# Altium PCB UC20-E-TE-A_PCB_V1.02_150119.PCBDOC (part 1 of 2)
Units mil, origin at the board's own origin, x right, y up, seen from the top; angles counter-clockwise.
Board outline 1460.63 x 2271.65 mil, 4 copper layers (Top, Inner Layer 2, Inner Layer 3, Bottom), stack 35.4 mil thick; 44 components, 79 nets, 323 pads, 599 vias.
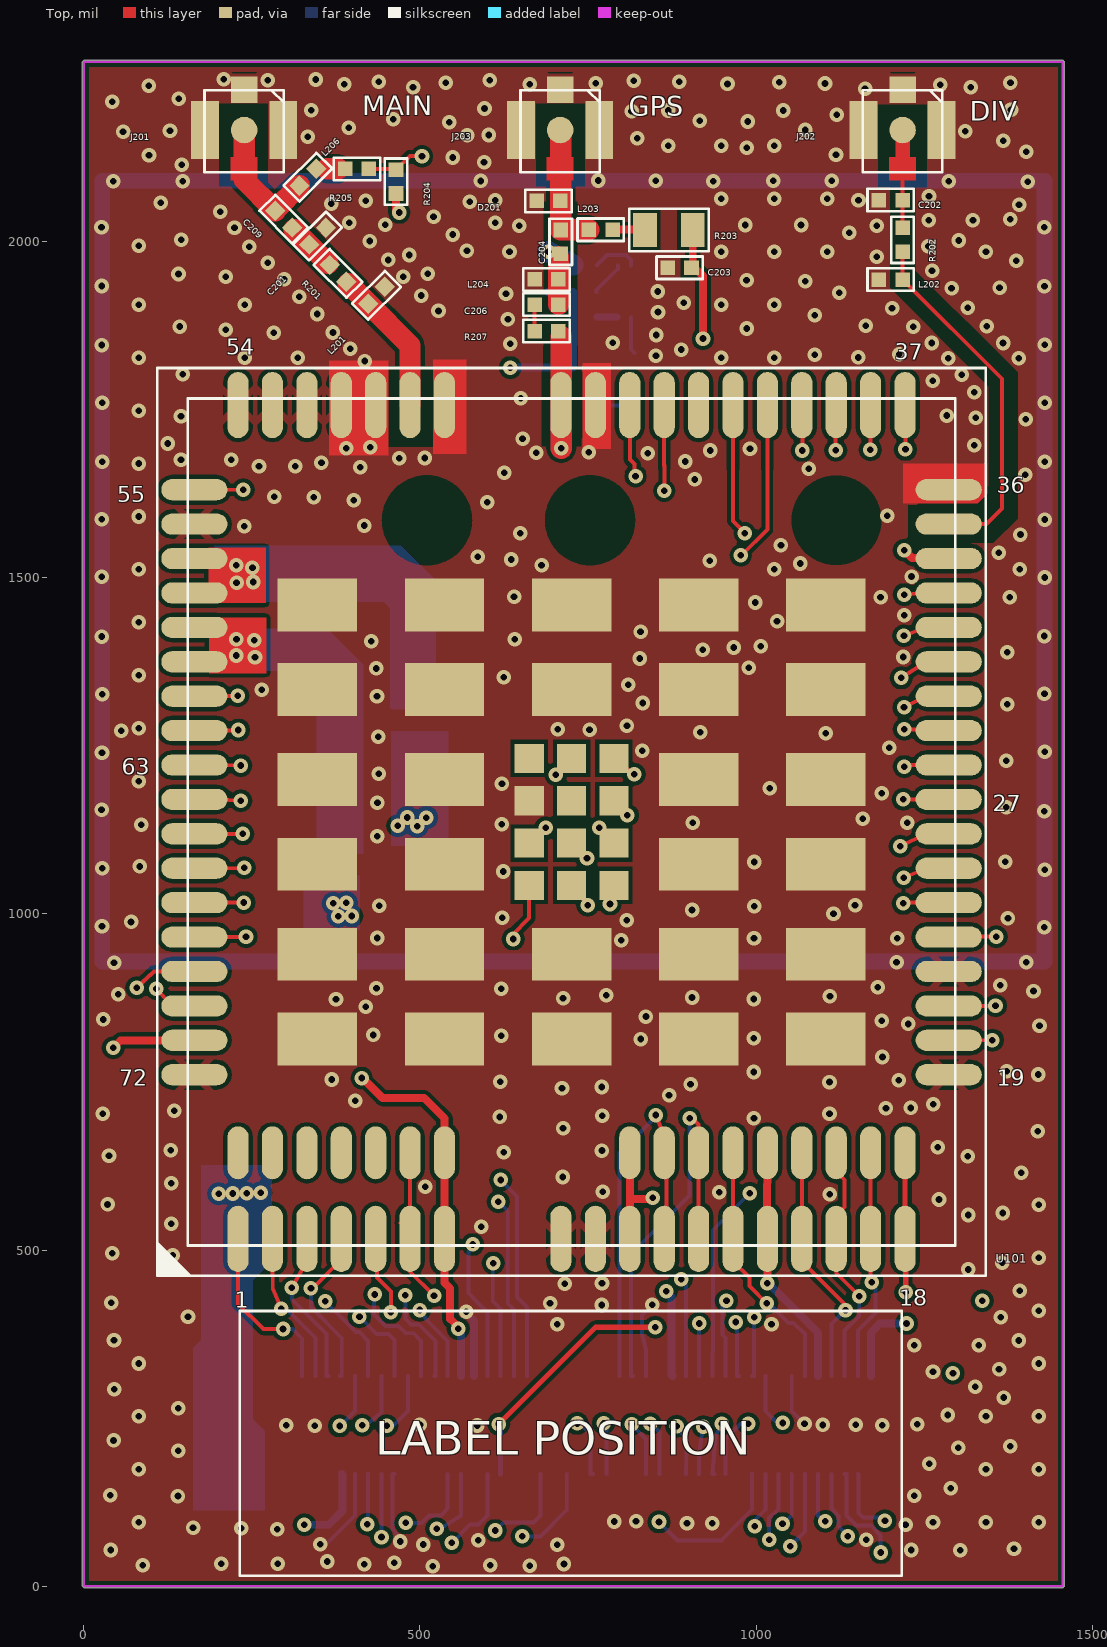
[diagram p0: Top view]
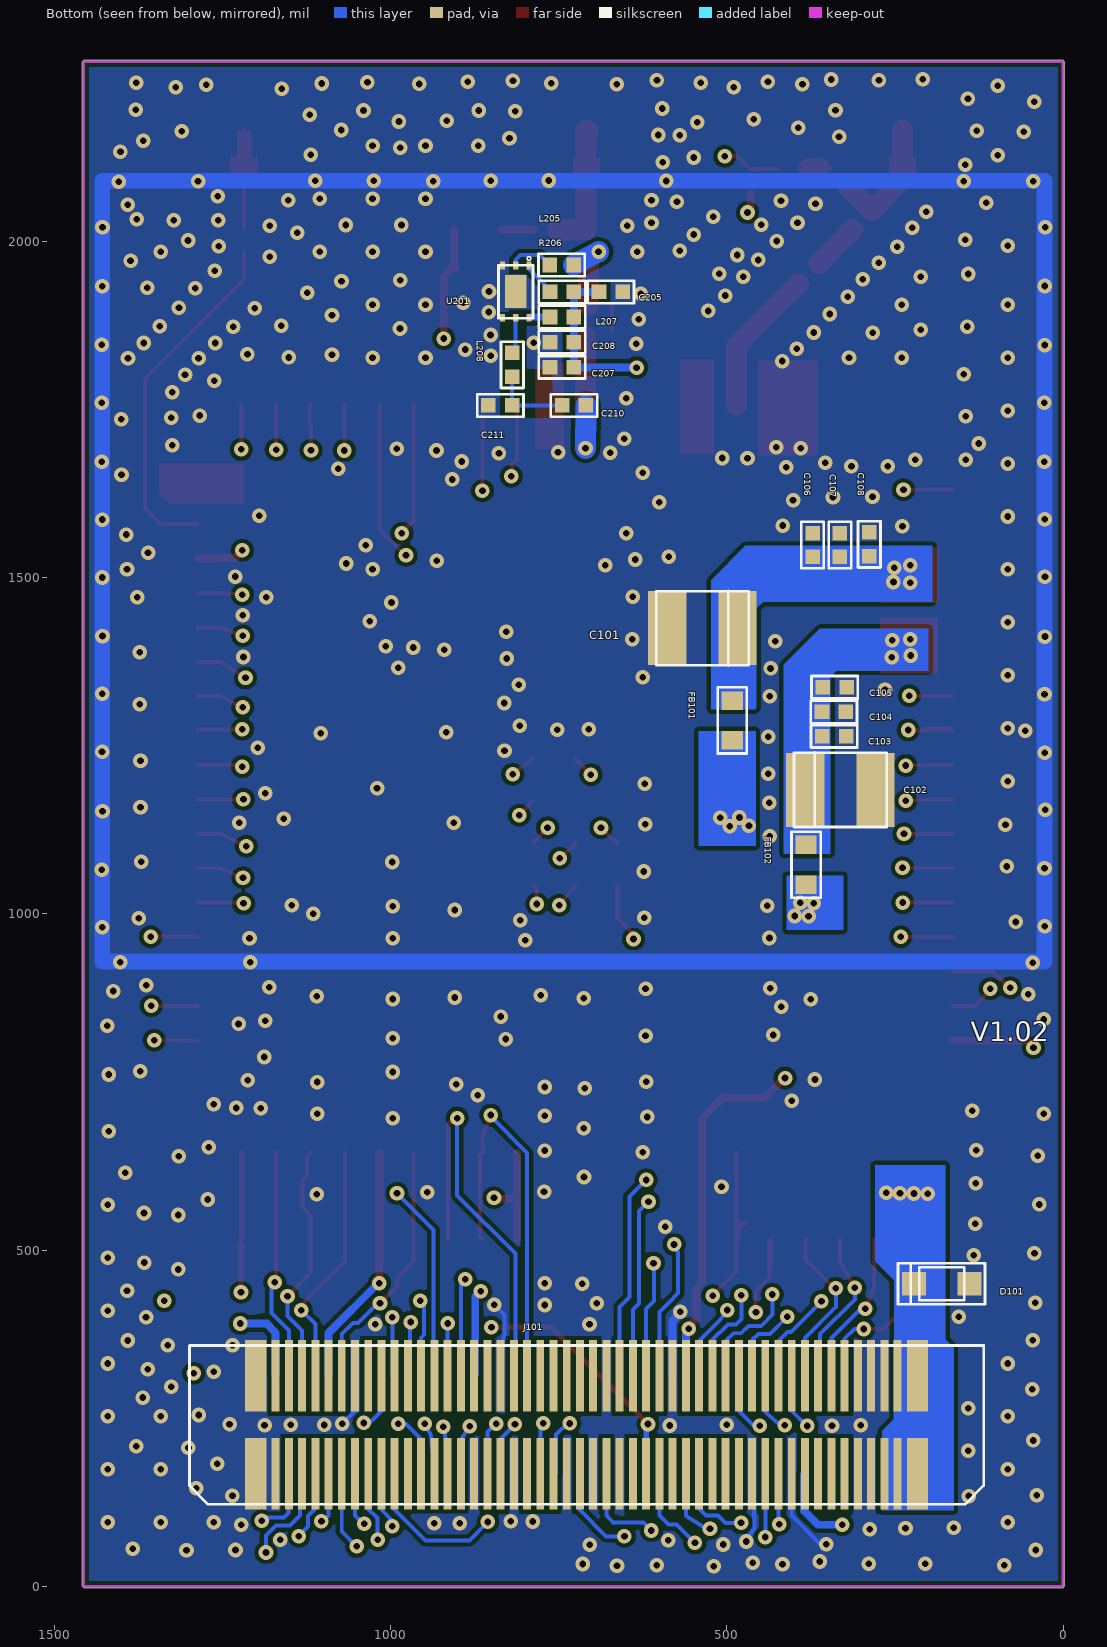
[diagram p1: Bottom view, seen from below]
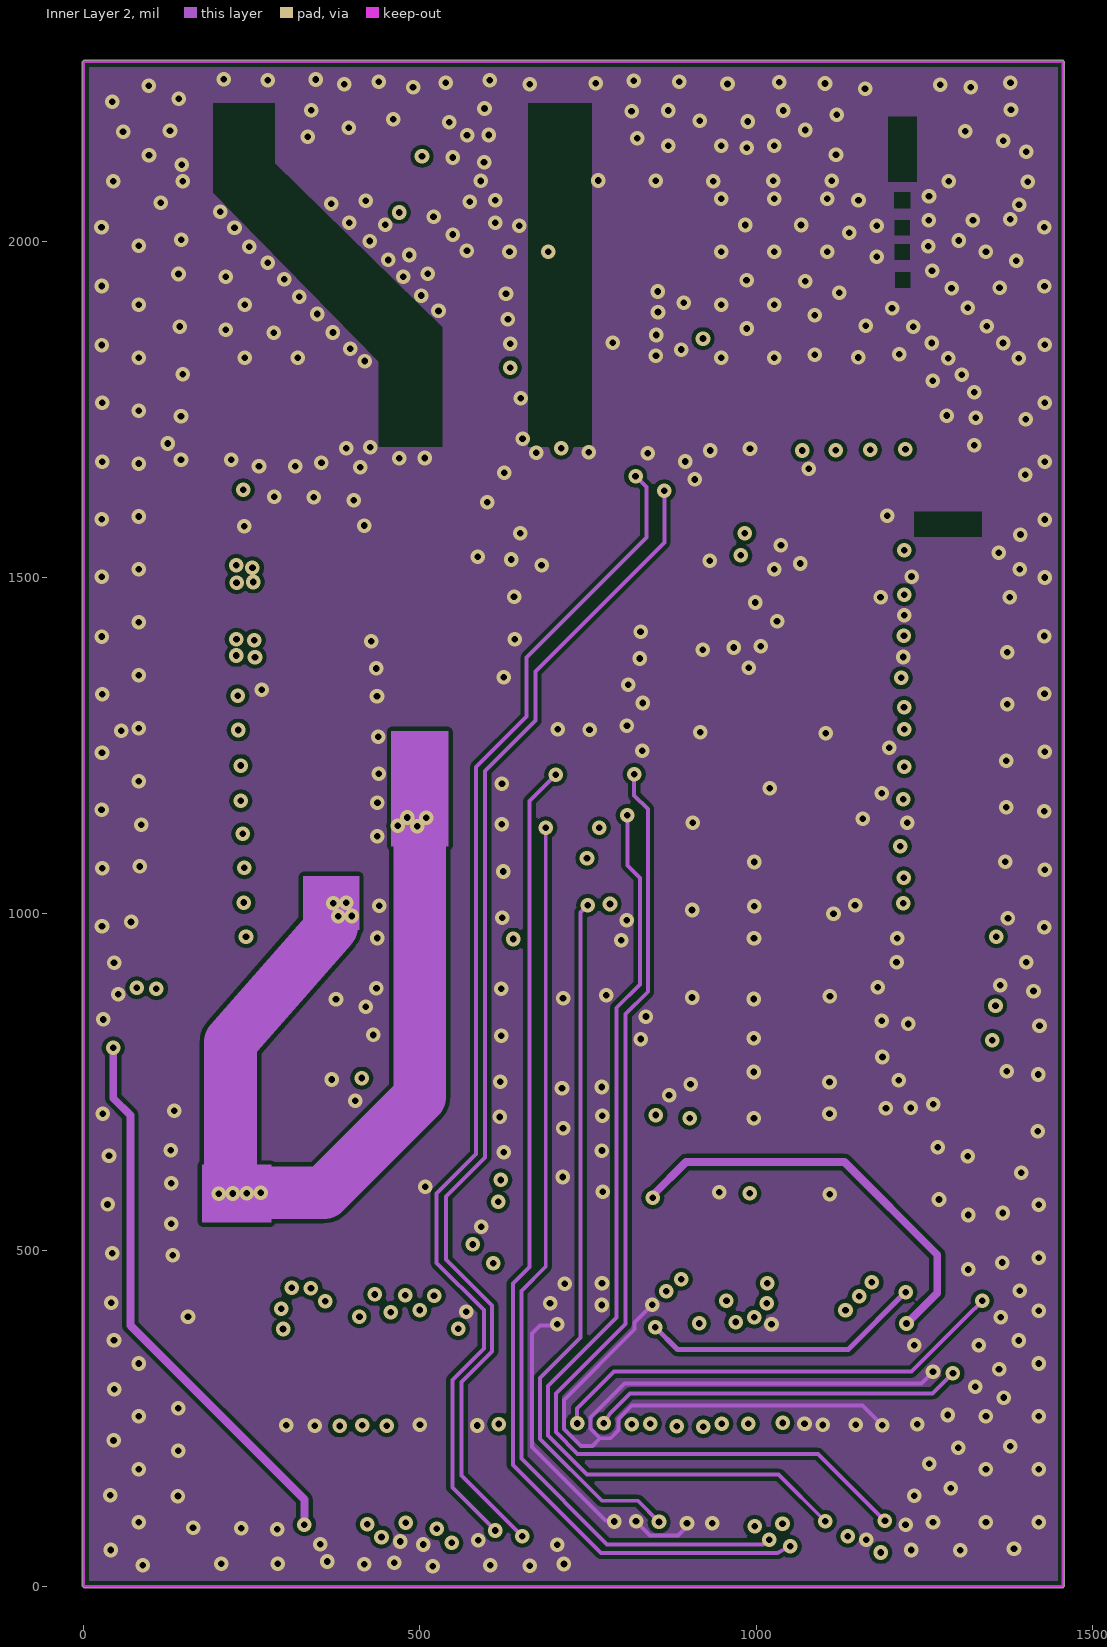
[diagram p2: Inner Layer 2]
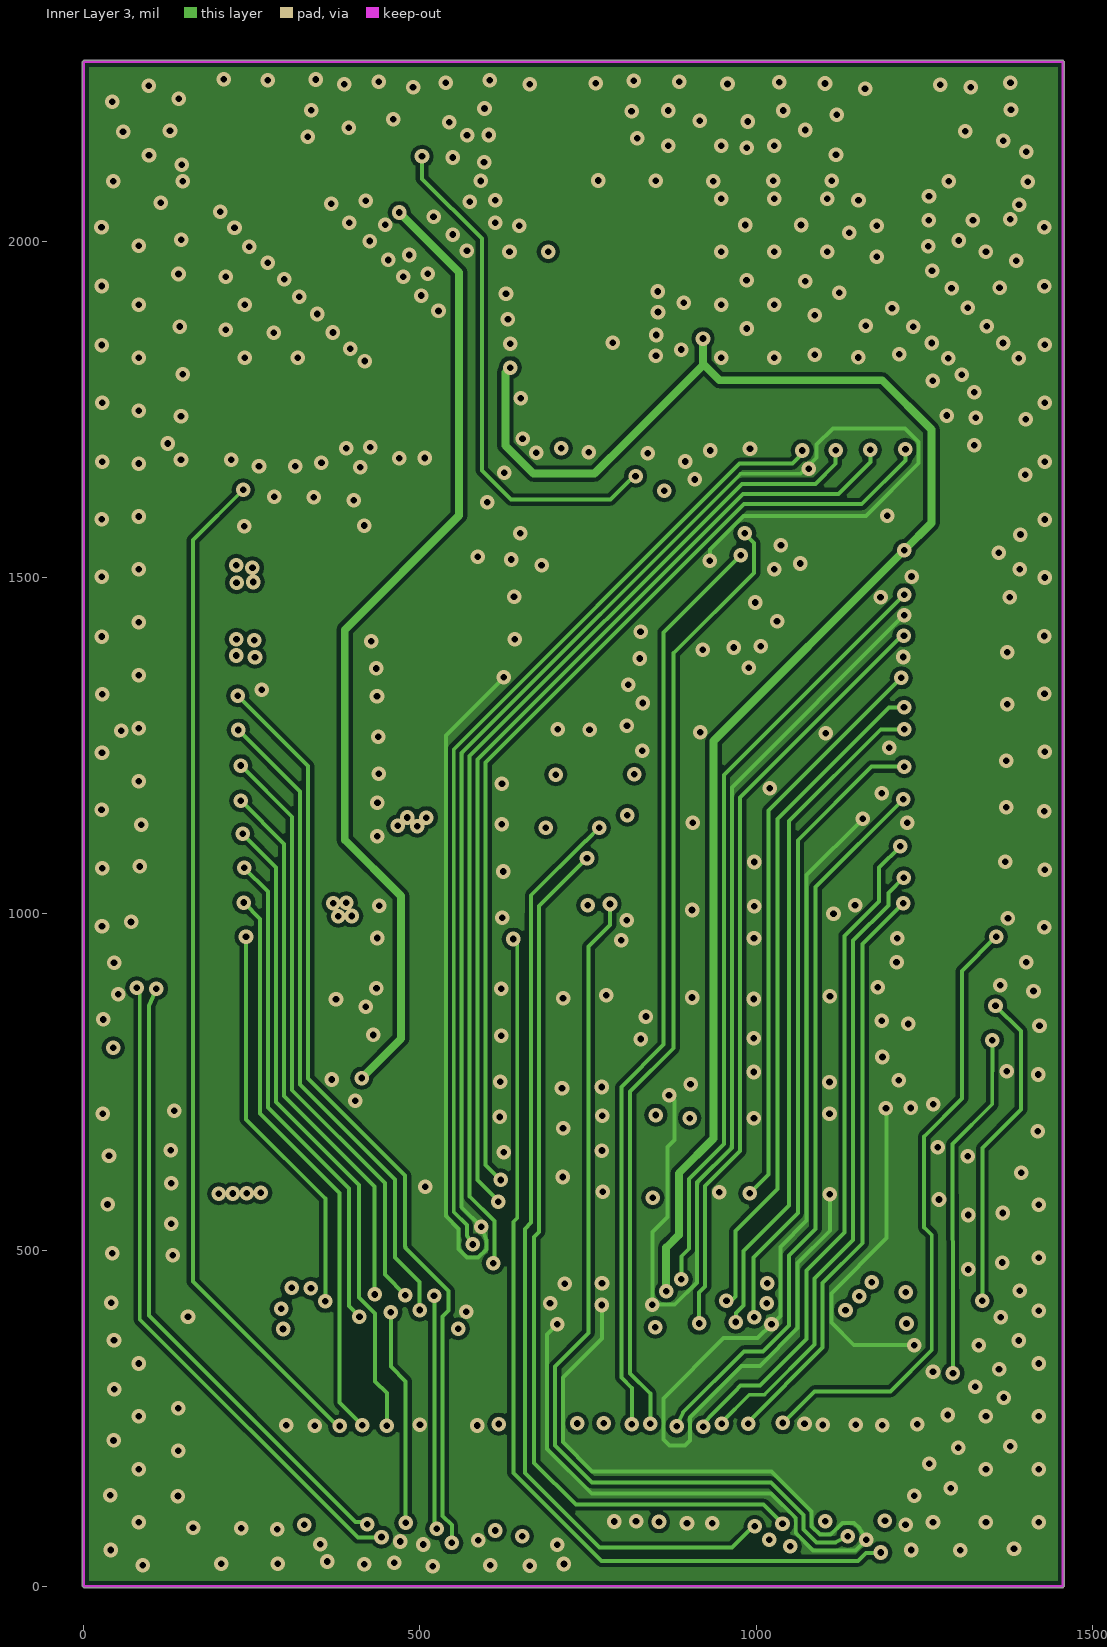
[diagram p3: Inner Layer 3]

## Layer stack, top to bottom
Top: signal copper 1.35
Dielectric: dielectric 10, FR-4, Dk 4.3
Inner Layer 2: signal copper 1.35
Dielectric: dielectric 10, FR-4, Dk 4.3
Inner Layer 3: signal copper 1.35
Dielectric: dielectric 10, FR-4, Dk 4.3
Bottom: signal copper 1.35

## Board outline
-1.97,0 0,-1.97 1456.69,-1.97 1458.66,0 1458.66,2267.72 1456.69,2269.68 0,2269.68 -1.97,2267.72

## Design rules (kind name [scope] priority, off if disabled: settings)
Clearance "'Default' PADS rule_18" [All] p1: gap=5.91
Clearance "'Default' PADS rule_15" [IsVia vs OnLayer(all)] p2: gap=0
ComponentClearance "'Default' PADS rule_12" [All] p1: gap=6 collisioncheckmode=3 verticalgap=10
FlightTimeFalling "'Default' PADS rule_6" [All] p1: maximum=10.00
FlightTimeRising "'Default' PADS rule_5" [All] p1: maximum=10.00
Length "'Default' PADS rule" [All] p1: maxlimit=50000 minlimit=0
MatchedLengths "'Default' PADS rule_7" [InNetClass('All Nets')] p1: tolerance=200 checknetsindiffpair=TRUE checkdiffpairvsdiffpair=TRUE checkothers=TRUE
MaxMinImpedance "'Default' PADS rule_4" [All] p1: minimum=50.00 maximum=150.0
ParallelSegment "'Default' PADS rule_3" [All] p1: limit=1000 gap=200
ParallelSegment "'Default' PADS rule_2" [All] p2: limit=1000 gap=200
PlaneClearance "'Net' PADS rule_34" [InNet('USB_DM')] p1: clearance=5.91
PlaneClearance "'Net' PADS rule_31" [InNet('$$$5208')] p2: clearance=5.91
PlaneClearance "'Net' PADS rule_27" [InNet('USB_DP')] p3: clearance=5.91
PlaneClearance "'Net' PADS rule_25" [InNet('ANT_MAIN')] p4: clearance=5.91
PlaneClearance "'Net' PADS rule_23" [InNet('GPS_IN')] p5: clearance=5.91
PlaneClearance "'Net' PADS rule_21" [InNet('$$$5265')] p6: clearance=5.91
PlaneClearance "'Net' PADS rule_19" [InNet('ANT_GPS')] p7: clearance=5.91
PlaneClearance "'Default' PADS rule_14" [All] p8: clearance=7.87
PlaneConnect "Power Plane Connect Style - from global settings" [All] p1: planeconnectstyle=Relief reliefexpansion=20 reliefentries=2 reliefconductorwidth=15 reliefairgap=10
PolygonConnect LCC [IsPad vs OnLayer('L1')] p1: connectstyle=Relief reliefconductorwidth=10 reliefentries=4 polygonreliefangle="45 Angle"
PolygonConnect PolygonConnect_1 [All] p2: connectstyle=Direct reliefconductorwidth=10 reliefentries=4 polygonreliefangle="90 Angle"
PolygonConnect LGA [IsPad] p3: connectstyle=Relief reliefconductorwidth=10 reliefentries=4 polygonreliefangle="45 Angle"
PolygonConnect GND-Via [IsVIA] p4: connectstyle=Direct reliefconductorwidth=10 reliefentries=4 polygonreliefangle="90 Angle"
PolygonConnect [All] p5: connectstyle=Direct reliefconductorwidth=10 reliefentries=4 polygonreliefangle="90 Angle"
RoutingLayers "'Default' PADS rule_10" [All] p1: top layer_v5=TRUE mid layer 1_v5=TRUE mid layer 2_v5=TRUE bottom layer_v5=TRUE
RoutingPriority "'Default' PADS rule_9" [All] p1: routingpriority=3
RoutingTopology "'Default' PADS rule_8" [All] p1: topology=Shortest
RoutingVias "'Default' PADS rule_11" [All] p1: holewidth=9.84 width=21.65 viastyle="Through Hole" minholewidth=9.84 minwidth=21.65 maxholewidth=9.84 maxwidth=21.65
SMDToCorner "'Default' PADS rule_16" [All] p1: distance=60000
SMDToPlane "'Default' PADS rule_17" [All] p1: distance=60000
SolderMaskExpansion [All] p1: expansion=4
TestPointUsage [All] p1: valid=0 allowmultiple=FALSE
Testpoint [All] p1: side=15 testpointundercomponent=TRUE minsize=40 maxsize=100 preferedsize=60 minholesize=0 maxholesize=40 preferedholesize=32 testpointgrid=1 style=1023 order=0-112345678
Width "'Net' PADS rule_33" [InNet('USB_DM')] p1: maxlimit=12 minlimit=3.94 preferedwidth=5.91
Width "'Net' PADS rule_32" [InNet('VDD_EXT')] p2: maxlimit=12 minlimit=3.94 preferedwidth=11.81
Width "'Net' PADS rule_30" [InNet('$$$5208')] p3: maxlimit=39.37 minlimit=3.94 preferedwidth=31.5
Width "'Net' PADS rule_29" [InNet('GND')] p4: maxlimit=12 minlimit=3.94 preferedwidth=5.91
Width "'Net' PADS rule_28" [InNet('SD_VDD')] p5: maxlimit=12 minlimit=3.94 preferedwidth=11.81
Width "'Net' PADS rule_26" [InNet('USB_DP')] p6: maxlimit=12 minlimit=3.94 preferedwidth=5.91
Width "'Net' PADS rule_24" [InNet('ANT_MAIN')] p7: maxlimit=39.37 minlimit=3.94 preferedwidth=31.5
Width "'Net' PADS rule_22" [InNet('GPS_IN')] p8: maxlimit=39.37 minlimit=3.94 preferedwidth=31.5
Width "'Net' PADS rule_20" [InNet('$$$5265')] p9: maxlimit=39.37 minlimit=3.94 preferedwidth=31.5
Width "'Net' PADS rule" [InNet('ANT_GPS')] p10: maxlimit=39.37 minlimit=3.94 preferedwidth=31.5
Width "'Default' PADS rule_13" [All] p11: maxlimit=31.5 minlimit=3.94 preferedwidth=5.91
13 further rules are at their usual default settings.

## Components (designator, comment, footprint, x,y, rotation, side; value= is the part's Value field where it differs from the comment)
C101 "3528T(B)-M" 3528T(B)-M 536.36,1425.12 r0 bottom
C102 "3528T(B)-M" 3528T(B)-M 331.18,1184.48 r180 bottom
C103 "C-0402" C-0402 340.43,1264.42 r180 bottom
C104 "C-0402" C-0402 340.83,1300.6 r180 bottom
C105 "C-0402" C-0402 339.63,1337.18 r180 bottom
C106 "C-0402" C-0402 372.43,1548.91 r90 bottom
C107 "C-0402" C-0402 331.99,1548.91 r90 bottom
C108 "C-0402" C-0402 288.19,1549.76 r90 bottom
C201 "C-0402" C-0402 347.83,2008.31 r45 top
C202 "C-0402" C-0402 1200.28,2061.73 r180 top
C203 "C-0402" C-0402 886.35,1961.29 r180 top
C204 "C-0402" C-0402 709.55,1999.65 r270 top
C205 "C-0402" C-0402 672.53,1925.34 r0 bottom
C206 "C-0402" C-0402 688.32,1906.44 r0 top
C207 "C-0402" C-0402 745.37,1813.14 r180 bottom
C208 "C-0402" C-0402 745.37,1850.54 r180 bottom
C209 "C-0402" C-0402 297.48,2033.54 r315 top
C210 "C-0402" C-0402 727.41,1756.46 r0 bottom
C211 "C-0402" C-0402 836.99,1756.43 r180 bottom
D101 "SOD-323" SOD-323 180.59,450.04 r180 bottom
D201 "C-0402" C-0402 691.34,2060.62 r0 top
FB101 "L-0603" L-0603 492.13,1287.95 r90 bottom
FB102 "L-0603" L-0603 382.2,1073.29 r90 bottom
J101 "AXK600347YG" AXK600347YG 708.66,240.16 r0 bottom
J201 "UFL-R-SMT-1" UFL-R-SMT-1 238.7,2166.06 r0 top
J202 "UFL-R-SMT-1" UFL-R-SMT-1 1217.99,2166.06 r0 top
J203 "UFL-R-SMT-1" UFL-R-SMT-1 708.66,2166.06 r0 top
L201 "L-0402" L-0402 435.54,1920.29 r45 top
L202 "L-0402" L-0402 1200.28,1943.62 r180 top
L203 "L-0402" L-0402 768.88,2017.78 r180 top
L204 "L-0402" L-0402 688.32,1943.9 r180 top
L205 "L-0402" L-0402 745.74,1965.31 r0 bottom
L206 "L-0402" L-0402 333.53,2095.97 r225 top
L207 "L-0402" L-0402 745.37,1887.94 r0 bottom
L208 "L-0402" L-0402 819.3,1816.77 r270 bottom
R201 "R-0402" R-0402 378.28,1952.82 r315 top
R202 "R-0402" R-0402 1217.99,2002.68 r270 top
R203 "R-0805" R-0805 870.5,2017.38 r0 top
R204 "R-0402" R-0402 464.53,2089.33 r270 top
R205 "R-0402" R-0402 406.59,2108.35 r0 top
R206 "R-0402" R-0402 745.37,1925.34 r0 bottom
R207 "R-0402" R-0402 688.32,1867.07 r0 top
U101 "UC20_M10" UC20_M10 154.78,507.03 r0 top
U201 "SKY65602-477LF" SKY65602-477LF 814.08,1925.66 r270 bottom

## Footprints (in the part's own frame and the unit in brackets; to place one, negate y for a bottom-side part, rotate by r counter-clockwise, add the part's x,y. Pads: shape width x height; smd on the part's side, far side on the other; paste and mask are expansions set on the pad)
3528T(B)-M [mm]
  rect 1.45x2.8 smd mask+0.05: 1(-1.325,0) 2(1.325,0)
  silkscreen extent -1.75,-1.41 1.75,1.42
AXK600347YG [mm]
  rect 0.8x2.7 smd paste-0.2 mask+0.015: 1(12.5,1.85) 2(12.5,-1.85) 99(-12.5,1.85) 100(-12.5,-1.85)
  rect 0.3x2.7 smd paste-0.2 mask+0.015: 3(11.75,1.85) 4(11.75,-1.85) 5(11.25,1.85) 6(11.25,-1.85) 7(10.75,1.85) 8(10.75,-1.85) 9(10.25,1.85) 10(10.25,-1.85) 11(9.75,1.85) 12(9.75,-1.85) 13(9.25,1.85) 14(9.25,-1.85) 15(8.75,1.85) 16(8.75,-1.85) 17(8.25,1.85) 18(8.25,-1.85) 19(7.75,1.85) 20(7.75,-1.85) 21(7.25,1.85) 22(7.25,-1.85) 23(6.75,1.85) 24(6.75,-1.85) 25(6.25,1.85) 26(6.25,-1.85) 27(5.75,1.85) 28(5.75,-1.85) 29(5.25,1.85) 30(5.25,-1.85) 31(4.75,1.85) 32(4.75,-1.85) 33(4.25,1.85) 34(4.25,-1.85) 35(3.75,1.85) 36(3.75,-1.85) 37(3.25,1.85) 38(3.25,-1.85) 39(2.75,1.85) 40(2.75,-1.85) 41(2.25,1.85) 42(2.25,-1.85) 43(1.75,1.85) 44(1.75,-1.85) 45(1.25,1.85) 46(1.25,-1.85) 47(0.75,1.85) 48(0.75,-1.85) 49(0.25,1.85) 50(0.25,-1.85) 51(-0.25,1.85) 52(-0.25,-1.85) 53(-0.75,1.85) 54(-0.75,-1.85) 55(-1.25,1.85) 56(-1.25,-1.85) 57(-1.75,1.85) 58(-1.75,-1.85) 59(-2.25,1.85) 60(-2.25,-1.85) 61(-2.75,1.85) 62(-2.75,-1.85) 63(-3.25,1.85) 64(-3.25,-1.85) 65(-3.75,1.85) 66(-3.75,-1.85) 67(-4.25,1.85) 68(-4.25,-1.85) 69(-4.75,1.85) 70(-4.75,-1.85) 71(-5.25,1.85) 72(-5.25,-1.85) 73(-5.75,1.85) 74(-5.75,-1.85) 75(-6.25,1.85) 76(-6.25,-1.85) 77(-6.75,1.85) 78(-6.75,-1.85) 79(-7.25,1.85) 80(-7.25,-1.85) 81(-7.75,1.85) 82(-7.75,-1.85) 83(-8.25,1.85) 84(-8.25,-1.85) 85(-8.75,1.85) 86(-8.75,-1.85) 87(-9.25,1.85) 88(-9.25,-1.85) 89(-9.75,1.85) 90(-9.75,-1.85) 91(-10.25,1.85) 92(-10.25,-1.85) 93(-10.75,1.85) 94(-10.75,-1.85) 95(-11.25,1.85) 96(-11.25,-1.85) 97(-11.75,1.85) 98(-11.75,-1.85)
  silkscreen extent -15,-3 15,3
C-0402 [mm]
  rect 0.55x0.55 smd mask+0.05: 1(-0.45,0) 2(0.45,0)
  silkscreen extent -0.87,-0.43 0.87,0.43
L-0402 [mm]
  rect 0.55x0.55 smd mask+0.05: 1(-0.45,0) 2(0.45,0)
  silkscreen extent -0.88,-0.42 0.88,0.42
L-0603 [mm]
  rect 0.7x0.8 smd mask+0.05: 1(-0.75,0) 2(0.75,0)
  silkscreen extent -1.25,-0.55 1.25,0.55
R-0402 [mm]
  rect 0.55x0.55 smd mask+0.05: 1(-0.45,0) 2(0.45,0)
  silkscreen extent -0.88,-0.42 0.88,0.42
R-0805 [mm]
  rect 0.9x1.3 smd mask+0.05: 1(-0.9,0) 2(0.9,0)
  silkscreen extent -1.5,-0.8 1.5,0.8
SKY65602-477LF [mm]
  rect 0.3x0.2 smd mask+0.025: 1(-0.985,0.5) 2(-0.985,0) 3(-0.985,-0.5) 4(0.985,-0.5) 5(0.985,0) 6(0.985,0.5)
  rect 1.25x0.8 smd mask+0.025: 7(0,0)
  silkscreen extent -1.32,-0.65 1,0.65
SOD-323 [mm]
  rect 0.9x0.9 smd mask+0.05: 1(-1.05,0) 2(1.05,0)
  silkscreen extent -1.65,-0.78 1.64,0.77
UC20_M10 [mm]
  oval 0.8x2.5 smd mask+0.05: 1(1.9,0.25) 2(3.2,0.25) 3(4.5,0.25) 4(5.8,0.25) 5(7.1,0.25) 6(8.4,0.25) 7(9.7,0.25) 8(14.1,0.25) 9(15.4,0.25) 10(16.7,0.25) 11(18,0.25) 12(19.3,0.25) 13(20.6,0.25) 14(21.9,0.25) 15(23.2,0.25) 16(24.5,0.25) 17(25.8,0.25) 18(27.1,0.25) 37(27.1,31.75) 38(25.8,31.75) 39(24.5,31.75) 40(23.2,31.75) 41(21.9,31.75) 42(20.6,31.75) 43(19.3,31.75) 44(18,31.75) 45(16.7,31.75) 46(15.4,31.75) 47(14.1,31.75) 48(9.7,31.75) 49(8.4,31.75) 50(7.1,31.75) 51(5.8,31.75) 52(4.5,31.75) 53(3.2,31.75) 54(1.9,31.75)
  oval 2.5x0.8 smd mask+0.05: 19(28.75,6.45) 20(28.75,7.75) 21(28.75,9.05) 22(28.75,10.35) 23(28.75,11.65) 24(28.75,12.95) 25(28.75,14.25) 26(28.75,15.55) 27(28.75,16.85) 28(28.75,18.15) 29(28.75,19.45) 30(28.75,20.75) 31(28.75,22.05) 32(28.75,23.35) 33(28.75,24.65) 34(28.75,25.95) 35(28.75,27.25) 36(28.75,28.55) 55(0.25,28.55) 56(0.25,27.25) 57(0.25,25.95) 58(0.25,24.65) 59(0.25,23.35) 60(0.25,22.05) 61(0.25,20.75) 62(0.25,19.45) 63(0.25,18.15) 64(0.25,16.85) 65(0.25,15.55) 66(0.25,14.25) 67(0.25,12.95) 68(0.25,11.65) 69(0.25,10.35) 70(0.25,9.05) 71(0.25,7.75) 72(0.25,6.45)
  oval 0.8x2 smd paste-0.075 mask+0.05: 73(1.9,3.5) 74(3.2,3.5) 75(4.5,3.5) 76(5.8,3.5) 77(7.1,3.5) 78(8.4,3.5) 79(9.7,3.5) 80(16.7,3.5) 81(18,3.5) 82(19.3,3.5) 83(20.6,3.5) 84(21.9,3.5) 85(23.2,3.5) 86(24.5,3.5) 87(25.8,3.5) 88(27.1,3.5)
  rect 1.1x1.1 smd mask+0.05: 89(12.9,18.4) 90(14.5,18.4) 91(16.1,18.4) 92(12.9,16.8) 93(14.5,16.8) 94(16.1,16.8) 95(12.9,15.2) 96(14.5,15.2) 97(16.1,15.2) 98(12.9,13.6) 99(14.5,13.6) 100(16.1,13.6)
  rect 3x2 smd mask+0.05: 101(4.9,24.2) 102(9.7,24.2) 103(14.5,24.2) 104(19.3,24.2) 105(24.1,24.2) 106(4.9,21) 107(9.7,21) 108(14.5,21) 109(19.3,21) 110(24.1,21) 111(4.9,17.6) 112(9.7,17.6) 113(19.3,17.6) 114(24.1,17.6) 115(4.9,14.4) 116(9.7,14.4) 117(19.3,14.4) 118(24.1,14.4) 119(4.9,11) 120(9.7,11) 121(14.5,11) 122(19.3,11) 123(24.1,11) 124(4.9,7.8) 125(9.7,7.8) 126(14.5,7.8) 127(19.3,7.8) 128(24.1,7.8)
  Top pour cut-out: 194 vertices and 0 holes, not listed, extent 22.8,25.697 26.2,29.097
  Top pour cut-out: 194 vertices and 0 holes, not listed, extent 13.5,25.697 16.9,29.097
  Top pour cut-out: 194 vertices and 0 holes, not listed, extent 7.339,25.697 10.739,29.097
  silkscreen extent -1.15,-1.15 30.15,33.15
UFL-R-SMT-1 [mm]
  round 1 smd: 1(0,0)
  rect 1.05x2.2 smd mask+0.05: 2(1.475,0) 4(-1.475,0)
  rect 1x1 smd mask+0.05: 3(0,1.525)
  Top region: -0.265,-0.05 0.265,-0.05 0.265,-1.523 -0.265,-1.523 -0.265,-0.05
  Top region: -0.499,-1.021 0.501,-1.021 0.501,-1.898 -0.499,-1.898 -0.499,-1.021
  silkscreen extent -1.5,-1.6 1.5,1.51

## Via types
v1: diameter 21.65, hole 9.84, Top to Bottom, 599 vias

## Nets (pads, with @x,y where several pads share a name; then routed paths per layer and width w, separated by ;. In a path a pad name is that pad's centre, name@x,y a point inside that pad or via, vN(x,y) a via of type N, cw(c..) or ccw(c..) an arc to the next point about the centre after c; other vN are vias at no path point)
$$$1337: L208.1 U201.5 | length 54.7
  Bottom w5.91: U201.5@814.08,1886.88 814.08,1839.48 814.32,1839.48 L208.1@819.3,1834.49
$$$4801: C210.2 C211.2 L208.2 | length 116.8
  Bottom w5.91: C210.2@745.13,1756.46 C211.2@819.25,1756.46 ; C211.2@819.3,1756.46 L208.2@819.3,1799.06
$$$5208: C201.1 C209.2 R201.1 | length 80.1
  Top w7.87: C209.2@310.01,2021.02 312.87,2018.15 C209.2@312.87,2017.65 ; R201.1@363.37,1967.73 R201.1@365.75,1965.35 R201.1@364.85,1965.68
  Top w31.5: C209.2@312.87,2017.65 313.45,2017.65 C201.1@335.31,1995.78 R201.1@363.37,1967.73
$$$5258: C202.1 J202.1 R202.1 | length 145.7
  Top w5.91: R202.1@1217.99,2020.39 C202.1@1217.99,2061.73 J202.1@1217.99,2166.06
$$$5265: C204.1 D201.2 J203.1 L203.2 | length 193.2
  Top w31.5: J203.1@707.09,2164.38 707.03,2164.44 J203.1@708.66,2166.06 709.55,2165.17 709.55,2060.62 C204.1@709.55,2017.36 709.97,2017.78 L203.2@751.17,2017.78
$$$6145: L203.1 R203.1 | length 48.6
  Top w11.81: L203.1@786.6,2017.78 834.66,2017.78 R203.1@835.07,2017.38
$$$7825: C206.1 R207.1 | length 39.4
  Top w5.91: R207.1@670.6,1867.07 C206.1@670.6,1906.44
$$$24864: C209.1 J201.1 L206.2 | length 191.5
  Top w31.5: J201.1@238.7,2166.06 238.7,2092.32 C209.1@284.95,2046.07 284.95,2047.39 L206.2@321,2083.44
$$$25611: L206.1 R205.1 | length 32.4
  Top w5.91: L206.1@346.06,2108.5 361.88,2108.5
  Top w31.5: 361.88,2108.5 R205.1@378.43,2108.5
$$$26819: L205.2 U201.2 | length 68
  Bottom w5.91: L205.2@763.45,1965.31 778.18,1980.04 806.69,1980.04 814.08,1972.65 U201.2@814.08,1964.44
$$$26984: R206.2 U201.1 | length 52.1
  Bottom w5.91: R206.2@763.08,1925.34 R206.2@763.08,1928.2 ; R206.2@763.07,1928.22 794.4,1959.54 U201.1@794.4,1964.44
$$$27295: L207.2 U201.6 | length 30.2
  Bottom w9.84: L207.2@763.08,1887.94 U201.6@793.33,1887.94
ADC0: J101.53 R204.1 R205.2 U101.45 | length 2881.7
  Top w5.91: R205.2@424.3,2108.35 458.75,2108.35 R204.1@459.35,2107.74 ; R204.1@459.39,2107.74 459.96,2107.17 463.7,2107.05 R204.1@464.53,2107.05 485.05,2127.57 502.48,2127.57 v1(503.21,2126.84) ; U101.45@812.26,1757.03 812.26,1676.17 819.32,1669.11 819.44,1652.65 v1(820.81,1651.24)
  Inner Layer 2 w5.91: v1(612.27,83.03) 548.62,146.68 548.62,307.21 595.32,353.9 595.32,410.81 524.98,481.15 524.98,584.3 583.75,643.07 583.75,1218.39 658.91,1293.54 658.91,1381.47 837.15,1559.71 837.15,1634.9 v1(820.81,1651.24)
  Inner Layer 3 w5.91: v1(503.21,2126.84) 503.21,2093.44 592.18,2004.48 592.18,1659.87 635.81,1616.23 783.3,1616.23 819.56,1652.49 v1(820.81,1651.24)
  Bottom w5.91: v1(612.27,83.03) 612.27,84.55 613.62,84.55 624.2,95.14 669.05,95.14 679.13,105.22 J101.53@679.13,167.32
ADC1: J101.49 U101.44 | length 2038.2
  Top w5.91: U101.44@863.44,1757.03 863.44,1667.02 863.57,1666.89 v1(863.57,1629.4)
  Inner Layer 2 w5.91: v1(652.36,74.32) 562.03,164.65 562.03,303.91 607.41,349.29 607.41,417.43 538.87,485.97 538.87,579.83 596.97,637.93 596.97,1212.72 671.88,1287.62 671.88,1360.52 672.63,1361.27 672.63,1361.44 863.57,1552.39 v1(863.57,1629.4)
  Bottom w5.91: v1(652.36,74.32) 679.48,74.32 718.5,113.34 J101.49@718.5,167.32
ANT_DIV: L202.1 R202.2 U101.35 | length 531.8
  Top w5.91: R202.2@1217.99,1984.96 L202.1@1217.99,1943.62 1218.11,1943.62 1365.63,1796.1 1365.63,1602.8 1342.7,1579.87 U101.35@1286.67,1579.87
ANT_GPS: C210.1 R207.2 U101.47 | length 240
  Top w7.87: R207.2@706.04,1867.07 R207.2@710.32,1858.75
  Top w31.5: v1(710.29,1692.69) 710.29,1756.64 U101.47@709.89,1757.03 710.32,1757.03 R207.2@710.32,1858.75
  Bottom w31.5: C210.1@709.7,1756.46 709.7,1721.28 710.29,1720.69 v1(710.29,1692.69)
ANT_MAIN: L201.1 R201.2 U101.49 | length 222.5
  Top w7.87: R201.2@390.81,1940.29 R201.2@393.61,1937.49
  Top w31.5: R201.2@393.61,1937.49 423.18,1907.93 485.49,1845.62 U101.49@485.49,1757.03
BOOT_KEY: J101.82 U101.55 | length 1672.6
  Top w5.91: U101.55@164.62,1631.05 198.08,1631.05 v1(237.34,1631)
  Inner Layer 3 w5.91: v1(237.34,1631) 162.64,1556.3 162.64,453.08 162.69,453.08 377.24,238.53 v1(380.63,238.53)
  Bottom w5.91: v1(380.63,238.53) 380.98,238.53 403.54,261.09 J101.82@403.54,312.99
CTS: J101.72 U101.64 | length 1054.9
  Top w5.91: U101.64@164.62,1170.42 198.08,1170.42 v1(233.74,1168.56)
  Inner Layer 3 w5.91: v1(233.74,1168.56) 298.07,1104.23 298.07,729.13 432.72,594.48 v1(432.72,434.12)
  Bottom w5.91: v1(432.72,434.12) 431.87,434.12 431.87,404.46 448.88,387.45 468.1,387.45 479.15,376.4 490.45,376.4 501.97,364.89 J101.72@501.97,312.99
DBG_RXD: J101.42 U101.11 U101.81 | length 613.8
  Top w5.91: v1(851.12,700.96) 863.44,668.45 U101.81@863.44,644.83 ; U101.81@862.68,658.19 861.84,658.15 U101.81@863.44,644.83 ; U101.11@863.44,516.88 866.98,520.42 866.98,641.29 U101.81@863.44,644.83
  Bottom w5.91: J101.42@797.24,312.99 797.24,644.67 851.12,698.55 v1(851.12,700.96)
DBG_TXD: J101.40 U101.12 U101.82 | length 609.2
  Top w5.91: v1(901.21,696.44) 904.8,696.44 914.62,686.62 U101.82@914.62,644.83 U101.12@914.62,516.88
  Bottom w5.91: J101.40@816.93,312.99 814.28,312.99 814.28,492.59 814.58,494.93 901.21,581.56 v1(901.21,696.44)
DCD: J101.70 U101.63 | length 1105.6
  Top w5.91: U101.63@164.62,1221.6 198.08,1221.6 v1(233.74,1220.8)
  Inner Layer 3 w5.91: v1(233.74,1220.8) 309.9,1144.64 309.9,737.83 447.9,599.83 447.9,463.46 v1(478.56,432.81)
  Bottom w5.91: v1(478.56,432.81) 478.56,397.82 486.74,389.63 498.65,389.63 523.39,364.89 523.39,312.99 J101.70@521.65,312.99
DTR: J101.76 U101.66 | length 947.7
  Top w5.91: U101.66@164.62,1068.06 238.79,1068.06 246.17,1068.06 v1(238.79,1068.74)
  Inner Layer 3 w5.91: v1(238.79,1068.74) 274.41,1033.12 274.41,711.87 394.37,591.91 394.37,416.78 v1(410.2,400.95)
  Bottom w5.91: v1(410.2,400.95) 435.78,375.37 453.28,375.37 462.6,366.05 J101.76@462.6,312.99
FLY_MODE: J101.84 U101.4 | length 247
  Top w5.91: v1(338.05,443.3) 339.29,442.06 383.12,485.89 U101.4@383.12,516.88
  Bottom w5.91: v1(338.05,443.3) 338.05,415.47 383.86,369.66 J101.84@383.86,312.99 J101.84@380.91,312.99
GND: C101.2 C102.2 C103.2 C104.2 C105.2 C106.2 C107.2 C108.2 C201.2 C202.2 C203.2 C205.1 C207.1 C208.1 C211.1 D101.2 D201.1 J101.1 J101.2 J101.3 J101.16 J101.33 J101.38 J101.39 J101.47 J101.51 J101.54 J101.55 J101.64 J101.75 J101.81 J101.91 J101.92 J101.93 J101.94 J101.96 J201.2 J201.3 J201.4 J202.2 J202.3 J202.4 J203.2 J203.3 J203.4 L201.2 L202.2 L204.2 U101.8 U101.9 U101.19 U101.22 U101.36 U101.46 U101.48 U101.50 U101.51 U101.52 U101.53 U101.54 U101.56 U101.72 U101.92 U101.101 U101.102 U101.103 U101.104 U101.105 U101.106 U101.107 U101.108 U101.109 U101.110 U101.111 U101.112 U101.113 U101.114 U101.115 U101.116 U101.117 U101.118 U101.119 U101.120 U101.121 U101.122 U101.123 U101.124 U101.125 U101.126 U101.127 U101.128 U201.3 U201.4 U201.7 | length 15620.5
  Inner Layer 2 w5.91: v1(704.34,389.84) 706.11,389.84 705.12,388.97 703.34,387.4 702.68,388.06 678.61,388.06 666.85,376.3 666.85,207.35 776.05,98.15 787.18,98.15 v1(788.94,96.39) ; v1(821.56,96.6) 842.65,75.51 883.92,75.51 897.33,88.92 v1(897.33,93.66) ; v1(845.88,419.06) 819.15,392.33 819.15,382.37 714.2,277.42 714.2,234.1 739.43,208.87 756.56,208.87 767.92,220.24 ; v1(1187.68,239.74) 1158.61,268.81 815.22,268.81 795.52,249.11 795.52,232.52 783.92,220.92 783.92,220.24 767.92,220.24 ; v1(1263.29,319.17) 1246.11,301.99 804.7,301.99 753.58,250.88 753.58,234.58 767.92,220.24
  Inner Layer 3 w5.91: v1(624.97,1351.98) 538.61,1265.61 538.61,550.77 557.65,531.73 557.65,501.57 570.45,488.77 586.75,488.77 598.83,500.85 598.83,515.06 591.94,534.84 v1(591.4,534.65) 562.23,563.82 562.23,1239.76 977.29,1654.82 1066.48,1654.82 1076,1664.33 1090.28,1678.61 1090.28,1698.11 1114.54,1722.38 1221.94,1722.38 1241.96,1702.36 1241.96,1670.43 1163.5,1591.98 1107.58,1591.98 1107.43,1591.84 981.12,1591.84 931.41,1542.12 v1(931.41,1525.13) ; v1(704.34,389.84) 689.24,374.74 689.24,204.54 755.72,138.06 1022.5,138.06 1059.12,101.44 1059.12,79.41 1085.1,53.44 1148.27,53.44 v1(1164.16,69.33) 1164.93,69.84 1153.74,86.62 1146.02,94.34 1128.45,94.34 1111.16,77.06 1094.88,77.06 1082.78,89.16 1082.78,111.18 1022.88,171.09 756.38,171.09 712.86,214.61 712.86,310.46 770.79,368.39 v1(770.79,418.43) ; v1(870.67,730.59) 878.44,722.82 878.44,663.52 868.27,653.35 868.27,549.34 845.88,526.95 v1(845.88,419.06) 879.15,419.06 912.28,452.19 912.28,600.58 964.02,652.31 964.02,1188.25 v1(1220.22,1444.45) ; v1(1109.95,583.22) 1109.95,528.87 1062.03,480.96 1062.03,384.12 1005.66,327.74 978.46,327.74 901.98,251.26 901.98,245.72 901.94,245.68 901.94,229.38 901.98,229.34 901.98,217.07 894.42,209.51 871.45,209.51 862.56,218.41 862.56,279.67 951.94,369.06 1002.43,369.06 v1(1023.02,389.65) 1023.66,389.01 1036.51,401.86 1036.51,504.99 1075.38,543.86 1075.38,1057.97 v1(1158.88,1141.47) ; v1@1194.23,708.31 1194.23,517.85 1112.01,435.63 1112.01,392.18 1145.59,358.6 v1(1235.35,358.6)
  Bottom w5.91: v1(352.08,62.85) 361.17,62.85 403.54,105.22 J101.81@403.54,167.32 ; J101.75@462.6,167.32 459.65,167.32 459.65,104.02 459.28,103.65 459.28,85.52 460.78,84.02 v1@472.53,67.79 ; J101.38@836.61,312.99 836.61,352.02 830.51,375.1 830.51,403.69 v1(845.88,419.06) ; J101.16@1053.15,312.99 1053.15,261.09 v1(1072.15,242.05) ; v1@472.53,67.79 v1(471.02,66.7) v1@472.53,67.79
  Bottom w11.81: v1(569.27,408.35) 568.3,407.38 580.71,394.97 J101.64@580.71,312.99
  Bottom w23.62: 27.56,929.13 45.17,929.13 1209.06,929.13 1402.03,929.13 1429.13,929.13 1429.13,980.5 1429.13,1066 1429.13,1153.07 1429.13,1241.05 1429.13,1327.43 1429.13,1413.44 v1(1429.2,1500.52) v1(1429.2,1586.72) 1429.13,1672.93 1429.13,1760.18 1429.13,1846.56 1429.13,1933.46 1429.13,2021.43 1429.13,2090.55 1404.33,2090.55 1286.6,2090.55 1112.51,2090.55 1025.45,2090.55 936.56,2090.55 851.08,2090.55 765.21,2090.55 590.42,2090.55 147.47,2090.55 44.19,2090.55 27.56,2090.55 27.56,2089.79 27.56,2021.65 27.56,1934.09 27.56,1846.25 27.56,1760.49 27.56,1672.64 27.56,1587.18 27.56,1501.51 27.56,1412.68 v1(27.61,1326.99) 27.56,1239.57 27.56,1154.83 v1(27.61,1067.87) 27.56,981.84 27.56,929.13
  other v1: 519.28,29.84 87.72,31.11 604.57,31.11 663.43,30.39 417.3,32.67 714.34,33.24 204.84,33.66 288.86,33.66 461.71,35.01 362,36.95 40.34,54 1230.89,54.03 1303.74,53.47 1383.76,56.01 505.14,62.22 704.19,61.74 586.93,68.4 287.77,85.03 234.37,86.25 162.65,86.89 1222.41,91.51 935.13,93.66 82.17,95.2 1263.27,95.2 1342.01,95.2 1420.75,95.2 140.25,134.27 1235.43,134.96 39.35,135.5 1289.47,146.06 82.17,173.94 1342.01,173.94 1420.75,173.94 1257.95,182.51 140.89,201.51 1300.84,206.3 1378.44,208.25 44.44,216.97 343.63,238.99 585.21,239.19 301.15,239.34 500.18,240.09 1099,240.03 1148.57,240.24 1239.73,241.16 82.17,252.68 1342.01,252.68 1420.75,252.68 1285.26,254.85 140.89,264.9 1368.69,280.76 45.71,293.36 1326.33,296.56 1361.51,323.07 82.17,331.42 1420.75,331.42 1331.42,358.65 45.06,365.91 1391.06,365.63 155.2,400.71 1363.95,400.48 1420.75,410.16 693.65,420.93 41.25,421.8 1392.18,439.5 715.35,450.08 770.95,450.9 1315.88,471.29 1366.39,481.56 1420.75,488.9 132.74,492.54 42.52,495.46 130.37,539.43 1315.88,552.27 1367,555.31 35.5,567.97 1420.75,567.64 1272.21,575.35 945.49,586.15 771.96,586.9 508.01,594.46 129.98,599.34 712.49,608.82 1394.66,615.03 1315.09,639.4 37.64,640.33 625.08,645.87 770.88,648.15 129.24,648.52 1270.43,652.9 1419.34,676.73 713.01,681.38 996.97,696.18 618.62,698.11 771.14,699.92 28.47,702.8 1109.36,702.62 134.96,707.19 1193.28,711.12 1229.96,711.52 1263.38,716.81 403.66,722.27 711.47,740.62 770.71,742.65 902.65,746.89 1109.35,750.04 619.79,750.36 1212.48,752.66 369.02,753.86 1419.61,761.26 996.77,764.98 1372.8,765.88 1188.08,787.31 828.78,814.03 996.92,815.39 620.97,819.04 430.96,820.08 1421.65,833.5 1226.33,836.46 1186.82,841.33 28.92,843.15 836.31,847.47 419.3,862.09 375.3,873.43 996.92,873.59 713.01,874.74 904.87,875.84 1109.98,877.84 777.01,879.09 51.63,880.84 1412.73,885.42 620.97,888.89 435.48,889.38 1180.92,890.93 1363.45,894.02 45.17,927.77 1209.06,928.24 1402.03,927.97 799.75,960.97 997.02,963.81 1210.09,963.67 436.68,964.3 1428.85,980.5 27.26,981.84 70.45,988.16 807.63,990.93 1374.75,993.52 622.73,994.55 1115.25,1000.38 904.87,1005.91 997.22,1011.31 439.86,1012.52 1147.31,1013.27 623.9,1063.23 1429.55,1066 83.68,1070.71 997.52,1077.32 1370.93,1077.54 436.39,1115.49 85.68,1132.76 621.55,1133.67 905.99,1135.97 1225.13,1135.72 1428.66,1153.07 26.59,1154.83 1372.21,1159.02 436.96,1165.46 1186.77,1179.4 1020.33,1187.05 622.14,1193.55 82.17,1197.56 438.67,1208.6 1372.21,1227.76 27.26,1239.57 1429.37,1241.05 830.77,1242.53 1197.94,1247.13 438.27,1263.6 1103.99,1269.11 917.32,1270.28 56.05,1272.57 752.42,1273.94 705.3,1274.71 82.17,1276.3 808.07,1280.05 1373.48,1311.78 831.27,1313.85 436.28,1323.78 1429.02,1327.43 264.83,1333.27 809.7,1340.71 82.17,1355.04 435.08,1365.23 988.94,1366.33 827.2,1380.03 1219.06,1382.21 1373.48,1389.43 920.62,1393.13 966.63,1396.42 1007.14,1398.46 427.91,1405.48 640.94,1408.82 26.9,1412.68 1428.66,1413.44 828.29,1419.55 82.17,1433.78 1031.3,1435.49 998.92,1463.29 1377.3,1470.91 640.12,1472.1 1185.22,1471.34 26.9,1501.51 1231.33,1501.9 82.17,1512.52 1027.05,1512.52 1392.3,1512.94 681.02,1518.77 1065.89,1521.29 636.1,1527.28 586.38,1531.21 1360.97,1537.21 1037.11,1548.5 1393.35,1564.4 649.54,1566.04 238.86,1576.89 417.1,1577.79 27.15,1587.18 82.17,1591.26 1195.39,1592.39 600.5,1612.7 401.58,1615.46 342.13,1619.97 283.42,1620.72 908.69,1646.31 1400.48,1653.21 625.34,1656.43 1078.32,1662.01 411.47,1664.3 260.76,1666.21 314.7,1666.04 82.17,1670 353.67,1671.33 27.76,1672.64 894.6,1673 1429.55,1672.93 144.78,1675.51 219.62,1675.51 469.36,1677.87 507.03,1678.2 673.29,1686.27 839,1685.38 751.13,1686.71 931.9,1689.4 991.09,1692.21 390.38,1692.95 426.43,1694.27 1324.7,1697.15 125.25,1699.78 652.74,1706.59 1400.96,1735.66 1326.65,1737.94 144.78,1740.26 1283.99,1741.39 82.17,1748.74 1429.72,1760.18 27.76,1760.49 649.95,1767.36 1324.71,1776.14 1262.73,1792.98 1305.93,1802.04 147.44,1803.01 417.86,1822.43 1285.86,1826.65 1390.75,1826.65 82.17,1827.48 239.65,1827.48 318.39,1827.48 948.31,1827.48 1027.05,1827.48 1151.92,1827.8 851.21,1830.11 1087.34,1831.71 1213.08,1832.45 889,1839.54 396.27,1840.73 27.15,1846.25 1429.55,1846.56 634.71,1848.41 787,1849.78 1261.25,1849.31 1367.44,1849.32 851.55,1861.22 282.85,1864.33 370.77,1864.93 211.54,1869.09 986.21,1870.85 1234.06,1873.27 142.77,1873.77 1343.49,1873.92 1163.01,1874.76 631.06,1884.66 1087.33,1890.42 347.23,1892.39 854.23,1895.34 527.72,1896.97 1202.33,1901.11 1315,1901.76 82.17,1906.22 239.65,1906.22 948.31,1906.22 1027.05,1906.22 892.27,1909.34 320.43,1917.9 502.2,1919.86 628.14,1922.45 1123.97,1924.1 853.86,1925.89 1290.84,1930.68 1362.26,1931.55 27.15,1934.09 1429.02,1933.46 1073.22,1941.05 985.92,1942.39 298.2,1944.06 211.53,1947.87 475.39,1947.98 141.06,1951.88 511.5,1952.53 1261.84,1956.65 274,1968.9 1386.98,1971.55 453.16,1972.82 1179.66,1977.52 484.44,1980.18 633.35,1984.96 948.31,1984.96 1027.05,1984.96 1105.79,1984.96 1342.01,1984.96 570.08,1986.51 246.54,1992.44 1256.02,1993.17 82.15,1994.15 425.71,2000.94 1301.48,2001.71 145.18,2002.9 549.02,2010.6 1138.78,2013.01 224.3,2020.55 26.55,2021.65 1428.66,2021.43 648.11,2023.48 1179.67,2023.49 448.63,2025.11 984.02,2024.81 1066.98,2024.81 394.97,2028.4 612.09,2028.43 1256.67,2031.64 1322.67,2032 1377.97,2033.29 520.4,2036.97 203.39,2044.75 1391.23,2054.78 368.16,2056.52 114.38,2057.89 574.27,2059.42 419.49,2060.72 612.11,2061.44 1152.47,2061.69 948.31,2063.7 1027.05,2063.7 1105.79,2063.7 1257.31,2067.52 44.19,2089.79 147.47,2089.86 936.56,2090.05 1286.6,2090.09 1404.33,2089.3 590.42,2090.33 765.21,2090.94 851.08,2090.84 1025.45,2090.77 1112.51,2090.42 145.72,2114.57 595.5,2117.95 549.12,2125.24 97.17,2128.3 1118.96,2129.25 1401.99,2133.99 986.01,2139.76 869.57,2142.44 948.31,2142.44 1027.05,2142.44 1367.9,2149.9 823.32,2153.87 333.18,2156.13 570.21,2158.52 602.23,2158.64 58.53,2163.54 1310.96,2164.16 128.39,2165.24 1073.39,2166.1 394,2169.54 543.87,2177.52 987.75,2178.71 916.46,2179.98 460.25,2182.31 1120.26,2188.73 814.87,2193.74 338.43,2195.25 869.29,2195.14 1040.52,2195.14 1379.26,2196.5 596.15,2198.1 42.62,2207.87 141.43,2212.68 1162.17,2227.22 489.89,2229.57 1319.69,2229.78 96.9,2231.65 387.61,2234.12 663.6,2234.26 1274.24,2233.58 957.57,2234.58 1102.61,2235.23 538.63,2236.2 761.37,2235.55 1034.62,2237.17 1378.45,2236.4 438.91,2238.14 885.7,2237.82 818.2,2239.2 273.8,2240.08 604.03,2240.08 344.95,2241.23 208.4,2241.38
GPS_IN: C204.2 C206.2 L204.1 L205.1 | length 113.3
  Top w31.5: C206.2@706.04,1906.44 L204.1@706.04,1943.9 C204.2@706.04,1977.7
  Bottom w31.5: v1(690.88,1985.03) L205.1@728.02,1965.31
I2C_SCL: J101.37 U101.41 | length 1697.5
  Top w5.91: v1(977.27,1533.38) 977.81,1532.84 1016.98,1572.01 U101.41@1016.98,1757.03
  Inner Layer 3 w5.91: v1(815.22,240.97) 815.22,295.17 799.69,310.71 799.69,742.8 862.52,805.63 862.52,1418.64 v1(977.27,1533.38)
  Bottom w5.91: v1(815.22,240.97) 814.58,241.33 815.08,240.83 836.61,219.3 J101.37@836.61,167.32
I2C_SDA: J101.35 U101.42 | length 1697.4
  Top w5.91: U101.42@965.8,1757.03 965.8,1584.38 983.35,1566.84 v1(983.35,1566.22)
  Inner Layer 3 w5.91: v1(842.79,241.69) 842.79,286.45 812.89,316.35 812.89,735.76 877.62,800.5 877.62,1387.87 996.96,1507.2 996.96,1551.86 v1(983.35,1566.22)
  Bottom w5.91: v1(842.79,241.69) 844.03,241.69 856.3,229.43 J101.35@856.3,167.32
